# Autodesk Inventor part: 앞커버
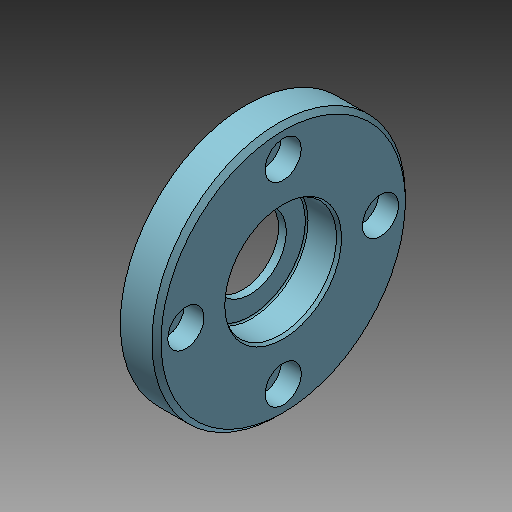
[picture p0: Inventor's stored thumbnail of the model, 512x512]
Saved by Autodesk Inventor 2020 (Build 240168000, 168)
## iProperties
Created: 2024-01
Part Number: 앞커버
Material: 알루미늄 6061
Document SubType Name: Modeling
Designer: mdu-01
Density: 1 g/cm^3
Appearance: 기본값(2)
Author: mdu-01
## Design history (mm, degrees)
sketch "스케치1"
  geometry: L1 (0, 0)-(-9, 0); L2 (-9, 0)-(-9, 14.5); L3 (-9, 14.5)-(-12, 14.5); L4 (-12, 14.5)-(-12, 16.5); L5 (-11, 17.5)-(-8, 17.5); L6 (-8, 17.5)-(-8, 28); L7 (-8, 28)-(-1, 28); L8 (0, 27)-(0, 0); L9 (-12, 16.5)-(-11, 17.5); L10 (-1, 28)-(0, 27); 2 further points
  constraints: 20 end point, 6 parallel, 4 point on line, 1 horizontal, 1 perpendicular
  dimensions: "d0" = 56 diameter of L7 L1; "d2" = 8 distance between parallel lines of L8 L6; "d3" = 3 distance between parallel lines of L2 L4; "d4" = 4 distance between parallel lines of L6 L4; "d5" = 29 diameter of L3 L1; "d6" = 35 diameter of L5 L1; "d7" = 1 distance of L4.end point (-12, 17.5); "d8" = 1 distance of L5.start point (-12, 17.5) (= d7); "d9" = 1 distance of L7.end point (0, 28) (= d7); "d10" = 1 distance of L8.start point (0, 28) (= d9)
revolve "회전1" sketch "스케치1" stored, may be unused: angle "d11" = 90 deg
sketch "스케치2" dims "d12" = 43
  geometry: 3 further points
  constraints: 2 vertical alignment, 1 coincident, 2 other
hole "구멍1" sketch "스케치2" at (0, 21.5) diameter "d13" = 4.5; stored, may be unused: countersink angle "d17" = 90 deg, drill point angle "d19" = 118 deg; dims "d14" = 6, "d15" = 8, "d16" = 4.4, "d18" = 8
sketch "스케치3"
  geometry: L1 (-9, -14.5)-(-9, 14.5) reference; L2 (0, -27)-(0, 27) reference; L3 (-9, 0)-(0, 0); L4 (0, 12.904)-(-0.7, 12.5); L5 (-0.7, 12.5)-(-7, 12.5); L6 (-7.3, 12.2)-(-7.3, 8); L7 (-7.3, 8)-(-9, 8); A1 r 0.3 centre (-7, 12.2) between (-7, 12.5) and (-7.3, 12.2)
  constraints: 10 end point, 3 perpendicular, 2 point on circle, 2 point on line, 2 tangent, 1 centre point, 1 midpoint, 1 parallel
  dimensions: "d23" = 30 deg angle of L5 L4; "d24" = 0.7 distance from line of L4.end L2; "d25" = 7.3 distance between parallel lines of L6 L2; "d26" = 25 diameter of L5 L3; "d27" = 0.3 radius of A1; "d28" = 16 diameter of L7 L3
revolve "회전2" sketch "스케치3" stored, may be unused: angle "d29" = 90 deg
node "솔리드1"
pattern_circular "원형 패턴1" dims angle "d21" = 360 deg
